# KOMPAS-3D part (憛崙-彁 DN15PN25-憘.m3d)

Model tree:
1. Объединить компоненты:1  (labels: СЕНС-ПР DN15PN25)
2. Эскиз:1
3. Операция выдавливания:1
     Расстояние 1 = 14; Расстояние 2 = 20.75
4. Фаска:1
     Угол = 45; Длина 1 = 2; Длина 2 = 2

Referenced files in D:\Савин\!СЕНСОР\3D для заказчика\!Новый перечень\СЕНС-ПР\1. СЕНС-ПР\DN15\: СЕНС-ПР DN15PN25.a3d
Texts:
  СЕНС-ПР DN15PN25-СВ
  ООО НПП Сенсор
  СЕНС-ПР DN15PN25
